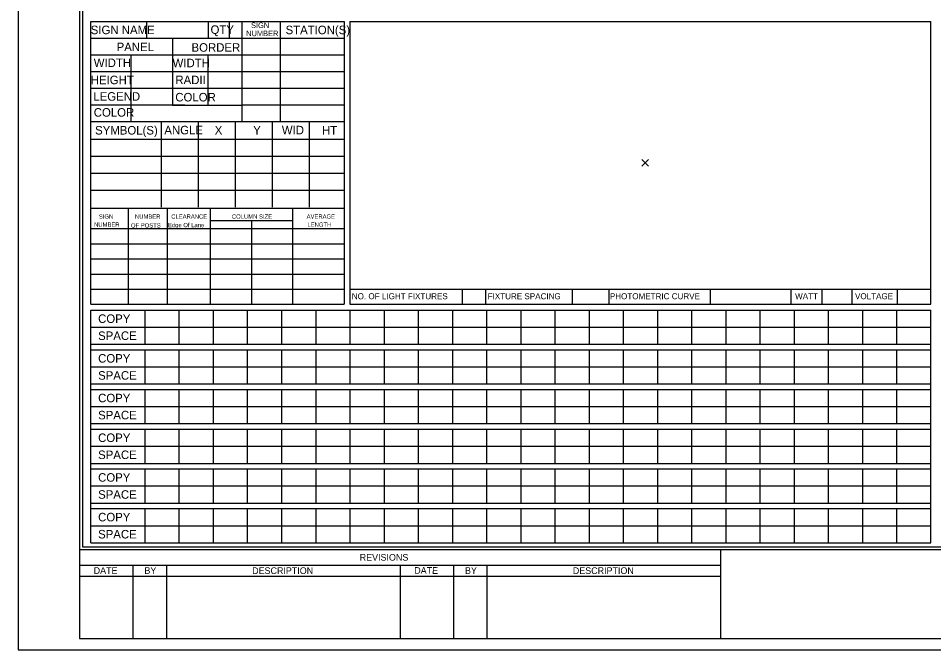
# Model space of a CAD drawing. Extents: x 1274.1 to 1363.1, y 833.5 to 890.6.
# Drawn here: x 1274.14 to 1318.48, y 833.48 to 864.07 of the extents above; entities that cross this region are included whole.
import ezdxf

# ---------------------------------------------------------------- set-up
doc = ezdxf.new("R2010")
doc.units = 0
for name, color, linetype in [('NonPlottingEle_dp', 7, 'Continuous'), ('PlotBorder_dp', 7, 'Continuous'), ('SheetBorder_dp', 7, 'Continuous'), ('SheetLines_dp', 7, 'Continuous'), ('SheetLinesMisc2_dp', 7, 'Continuous'), ('TextMinor', 7, 'Continuous'), ('TextMisc', 7, 'Continuous')]:
    doc.layers.add(name, color=color, linetype=linetype)

msp = doc.modelspace()

# ---------------------------------------------------------------- linework, layer by layer
at = {"layer": 'NonPlottingEle_dp'}
for p, q in [((1304.339, 857.226), (1304.66, 856.905)), ((1304.339, 856.905), (1304.66, 857.226))]:
    msp.add_line(p, q, dxfattribs=at)
at = {"layer": 'PlotBorder_dp'}
msp.add_lwpolyline([(1274.135, 833.481), (1363.097, 833.481), (1363.097, 890.634), (1274.135, 890.634)], close=True, dxfattribs=at)
at = {"layer": 'SheetBorder_dp'}
for p, q in [((1277.101, 890.095), (1277.101, 834.02)), ((1277.101, 838.334), (1360.132, 838.334)), ((1277.101, 834.02), (1360.132, 834.02))]:
    msp.add_line(p, q, dxfattribs=at)
at = {"layer": 'SheetLines_dp'}
for p, q in [((1308.156, 838.334), (1308.156, 834.02)), ((1277.101, 837.579), (1308.156, 837.579)), ((1279.689, 837.579), (1279.689, 834.02)), ((1281.306, 837.579), (1281.306, 834.02)), ((1292.628, 837.579), (1292.628, 834.02)), ((1295.216, 837.579), (1295.216, 834.02)), ((1296.834, 837.579), (1296.834, 834.02)), ((1277.101, 837.04), (1308.156, 837.04))]:
    msp.add_line(p, q, dxfattribs=at)
at = {"layer": 'SheetLinesMisc2_dp'}
for p, q in [((1277.247, 889.967), (1277.247, 838.462)), ((1277.644, 850.212), (1277.644, 863.919)), ((1277.644, 863.919), (1289.912, 863.919)), ((1280.348, 863.919), (1280.348, 863.109)), ((1283.331, 863.919), (1283.331, 863.109)), ((1284.349, 863.919), (1284.349, 863.109)), ((1284.956, 863.919), (1284.956, 859.061)), ((1286.823, 863.919), (1286.823, 859.061)), ((1289.912, 863.919), (1289.912, 850.212)), ((1290.195, 863.919), (1318.336, 863.919)), ((1290.195, 863.919), (1290.195, 850.231)), ((1318.336, 850.231), (1318.336, 863.92)), ((1277.644, 863.109), (1289.912, 863.109)), ((1281.609, 863.109), (1281.609, 859.862)), ((1277.644, 862.3), (1289.912, 862.3)), ((1279.583, 862.3), (1279.583, 859.061)), ((1283.32, 862.291), (1283.32, 859.862)), ((1277.644, 861.49), (1289.912, 861.49)), ((1277.644, 860.68), (1289.912, 860.68)), ((1277.644, 859.871), (1282.194, 859.871)), ((1281.609, 859.862), (1284.956, 859.862)), ((1284.956, 859.871), (1289.912, 859.871)), ((1277.644, 859.061), (1289.912, 859.061)), ((1281.051, 859.045), (1281.051, 854.911)), ((1282.844, 859.045), (1282.844, 854.911)), ((1284.636, 859.045), (1284.636, 854.911)), ((1286.429, 859.045), (1286.429, 854.911)), ((1288.221, 859.045), (1288.221, 854.911)), ((1277.647, 858.218), (1289.912, 858.218)), ((1277.647, 857.391), (1289.912, 857.391)), ((1277.647, 856.565), (1289.912, 856.565)), ((1277.647, 855.738), (1289.912, 855.738)), ((1277.644, 854.872), (1289.912, 854.872)), ((1279.464, 854.872), (1279.464, 850.212)), ((1281.346, 854.872), (1281.346, 850.212)), ((1283.424, 854.872), (1283.424, 850.212)), ((1287.425, 854.872), (1287.425, 850.212)), ((1283.424, 854.279), (1287.422, 854.279)), ((1285.432, 854.279), (1285.432, 850.212)), ((1277.644, 853.884), (1289.912, 853.884)), ((1277.644, 853.149), (1289.912, 853.149)), ((1277.644, 852.415), (1289.912, 852.415)), ((1277.644, 851.68), (1289.912, 851.68)), ((1277.644, 850.946), (1289.912, 850.946)), ((1290.196, 850.946), (1318.336, 850.946)), ((1295.631, 850.946), (1295.631, 850.212)), ((1296.77, 850.946), (1296.77, 850.212)), ((1300.96, 850.946), (1300.96, 850.212)), ((1302.744, 850.946), (1302.744, 850.212)), ((1307.643, 850.946), (1307.643, 850.212)), ((1311.554, 850.946), (1311.554, 850.212)), ((1313.064, 850.946), (1313.064, 850.212)), ((1314.519, 850.946), (1314.519, 850.212)), ((1316.711, 850.946), (1316.711, 850.212)), ((1277.644, 850.212), (1289.912, 850.212)), ((1290.195, 850.231), (1290.195, 850.213)), ((1290.196, 850.212), (1318.336, 850.212)), ((1318.336, 850.213), (1318.336, 850.231)), ((1277.644, 849.93), (1318.336, 849.93)), ((1277.644, 838.662), (1277.644, 849.93)), ((1280.263, 849.93), (1280.263, 848.276)), ((1281.919, 849.93), (1281.919, 848.276)), ((1283.574, 849.93), (1283.574, 848.276)), ((1285.229, 849.93), (1285.229, 848.276)), ((1286.885, 849.93), (1286.885, 848.276)), ((1288.54, 849.93), (1288.54, 848.276)), ((1290.196, 849.93), (1290.196, 848.276)), ((1291.851, 849.93), (1291.851, 848.276)), ((1293.506, 849.93), (1293.506, 848.276)), ((1295.161, 849.93), (1295.161, 848.276)), ((1296.817, 849.93), (1296.817, 848.276)), ((1298.472, 849.93), (1298.472, 848.276)), ((1300.127, 849.93), (1300.127, 848.276)), ((1301.783, 849.93), (1301.783, 848.276)), ((1303.438, 849.93), (1303.438, 848.276)), ((1305.093, 849.93), (1305.093, 848.276)), ((1306.749, 849.93), (1306.749, 848.276)), ((1308.404, 849.93), (1308.404, 848.276)), ((1310.06, 849.93), (1310.06, 848.276)), ((1311.715, 849.93), (1311.715, 848.276)), ((1313.37, 849.93), (1313.37, 848.276)), ((1315.025, 849.93), (1315.025, 848.276)), ((1316.681, 849.93), (1316.681, 848.276)), ((1318.336, 838.662), (1318.336, 849.93)), ((1277.644, 849.103), (1318.336, 849.103)), ((1277.644, 848.276), (1318.336, 848.276)), ((1277.644, 848.007), (1318.336, 848.007)), ((1280.263, 848.007), (1280.263, 846.353)), ((1281.919, 848.007), (1281.919, 846.353)), ((1283.574, 848.007), (1283.574, 846.353)), ((1285.229, 848.007), (1285.229, 846.353)), ((1286.885, 848.007), (1286.885, 846.353)), ((1288.54, 848.007), (1288.54, 846.353)), ((1290.196, 848.007), (1290.196, 846.353)), ((1291.851, 848.007), (1291.851, 846.353)), ((1293.506, 848.007), (1293.506, 846.353)), ((1295.161, 848.007), (1295.161, 846.353)), ((1296.817, 848.007), (1296.817, 846.353)), ((1298.472, 848.007), (1298.472, 846.353)), ((1300.127, 848.007), (1300.127, 846.353)), ((1301.783, 848.007), (1301.783, 846.353)), ((1303.438, 848.007), (1303.438, 846.353)), ((1305.093, 848.007), (1305.093, 846.353)), ((1306.749, 848.007), (1306.749, 846.353)), ((1308.404, 848.007), (1308.404, 846.353)), ((1310.06, 848.007), (1310.06, 846.353)), ((1311.715, 848.007), (1311.715, 846.353)), ((1313.37, 848.007), (1313.37, 846.353)), ((1315.025, 848.007), (1315.025, 846.353)), ((1316.681, 848.007), (1316.681, 846.353)), ((1277.644, 847.18), (1318.336, 847.18)), ((1277.644, 846.353), (1318.336, 846.353)), ((1277.644, 846.084), (1318.336, 846.084)), ((1280.263, 846.084), (1280.263, 844.431)), ((1281.919, 846.084), (1281.919, 844.431)), ((1283.574, 846.084), (1283.574, 844.431)), ((1285.229, 846.084), (1285.229, 844.431)), ((1286.885, 846.084), (1286.885, 844.431)), ((1288.54, 846.084), (1288.54, 844.431)), ((1290.196, 846.084), (1290.196, 844.431)), ((1291.851, 846.084), (1291.851, 844.431)), ((1293.506, 846.084), (1293.506, 844.431)), ((1295.161, 846.084), (1295.161, 844.431)), ((1296.817, 846.084), (1296.817, 844.431)), ((1298.472, 846.084), (1298.472, 844.431)), ((1300.127, 846.084), (1300.127, 844.431)), ((1301.783, 846.084), (1301.783, 844.431)), ((1303.438, 846.084), (1303.438, 844.431)), ((1305.093, 846.084), (1305.093, 844.431)), ((1306.749, 846.084), (1306.749, 844.431)), ((1308.404, 846.084), (1308.404, 844.431)), ((1310.06, 846.084), (1310.06, 844.431)), ((1311.715, 846.084), (1311.715, 844.431)), ((1313.37, 846.084), (1313.37, 844.431)), ((1315.025, 846.084), (1315.025, 844.431)), ((1316.681, 846.084), (1316.681, 844.431)), ((1277.644, 845.257), (1318.336, 845.257)), ((1277.644, 844.431), (1318.336, 844.431)), ((1277.644, 844.161), (1318.336, 844.161)), ((1280.263, 844.161), (1280.263, 842.508)), ((1281.919, 844.161), (1281.919, 842.508)), ((1283.574, 844.161), (1283.574, 842.508)), ((1285.229, 844.161), (1285.229, 842.508)), ((1286.885, 844.161), (1286.885, 842.508)), ((1288.54, 844.161), (1288.54, 842.508)), ((1290.196, 844.161), (1290.196, 842.508)), ((1291.851, 844.161), (1291.851, 842.508)), ((1293.506, 844.161), (1293.506, 842.508)), ((1295.161, 844.161), (1295.161, 842.508)), ((1296.817, 844.161), (1296.817, 842.508)), ((1298.472, 844.161), (1298.472, 842.508)), ((1300.127, 844.161), (1300.127, 842.508)), ((1301.783, 844.161), (1301.783, 842.508)), ((1303.438, 844.161), (1303.438, 842.508)), ((1305.093, 844.161), (1305.093, 842.508)), ((1306.749, 844.161), (1306.749, 842.508)), ((1308.404, 844.161), (1308.404, 842.508)), ((1310.06, 844.161), (1310.06, 842.508)), ((1311.715, 844.161), (1311.715, 842.508)), ((1313.37, 844.161), (1313.37, 842.508)), ((1315.025, 844.161), (1315.025, 842.508)), ((1316.681, 844.161), (1316.681, 842.508)), ((1277.644, 843.335), (1318.336, 843.335)), ((1277.644, 842.508), (1318.336, 842.508)), ((1277.644, 842.238), (1318.336, 842.238)), ((1280.263, 842.238), (1280.263, 840.585)), ((1281.919, 842.238), (1281.919, 840.585)), ((1283.574, 842.238), (1283.574, 840.585)), ((1285.229, 842.238), (1285.229, 840.585)), ((1286.885, 842.238), (1286.885, 840.585)), ((1288.54, 842.238), (1288.54, 840.585)), ((1290.196, 842.238), (1290.196, 840.585)), ((1291.851, 842.238), (1291.851, 840.585)), ((1293.506, 842.238), (1293.506, 840.585)), ((1295.161, 842.238), (1295.161, 840.585)), ((1296.817, 842.238), (1296.817, 840.585)), ((1298.472, 842.238), (1298.472, 840.585)), ((1300.127, 842.238), (1300.127, 840.585)), ((1301.783, 842.238), (1301.783, 840.585)), ((1303.438, 842.238), (1303.438, 840.585)), ((1305.093, 842.238), (1305.093, 840.585)), ((1306.749, 842.238), (1306.749, 840.585)), ((1308.404, 842.238), (1308.404, 840.585)), ((1310.06, 842.238), (1310.06, 840.585)), ((1311.715, 842.238), (1311.715, 840.585)), ((1313.37, 842.238), (1313.37, 840.585)), ((1315.025, 842.238), (1315.025, 840.585)), ((1316.681, 842.238), (1316.681, 840.585)), ((1277.644, 841.411), (1318.336, 841.411)), ((1277.644, 840.585), (1318.336, 840.585)), ((1277.644, 840.315), (1318.336, 840.315)), ((1280.263, 840.315), (1280.263, 838.662)), ((1281.919, 840.315), (1281.919, 838.662)), ((1283.574, 840.315), (1283.574, 838.662)), ((1285.229, 840.315), (1285.229, 838.662)), ((1286.885, 840.315), (1286.885, 838.662)), ((1288.54, 840.315), (1288.54, 838.662)), ((1290.196, 840.315), (1290.196, 838.662)), ((1291.851, 840.315), (1291.851, 838.662)), ((1293.506, 840.315), (1293.506, 838.662)), ((1295.161, 840.315), (1295.161, 838.662)), ((1296.817, 840.315), (1296.817, 838.662)), ((1298.472, 840.315), (1298.472, 838.662)), ((1300.127, 840.315), (1300.127, 838.662)), ((1301.783, 840.315), (1301.783, 838.662)), ((1303.438, 840.315), (1303.438, 838.662)), ((1305.093, 840.315), (1305.093, 838.662)), ((1306.749, 840.315), (1306.749, 838.662)), ((1308.404, 840.315), (1308.404, 838.662)), ((1310.06, 840.315), (1310.06, 838.662)), ((1311.715, 840.315), (1311.715, 838.662)), ((1313.37, 840.315), (1313.37, 838.662)), ((1315.025, 840.315), (1315.025, 838.662)), ((1316.681, 840.315), (1316.681, 838.662)), ((1277.644, 839.489), (1318.336, 839.489)), ((1277.644, 838.662), (1318.336, 838.662)), ((1277.247, 838.462), (1359.988, 838.462))]:
    msp.add_line(p, q, dxfattribs=at)

# ---------------------------------------------------------------- texts
at = {"layer": 'TextMinor'}
for s, height, p in [('SIGN', 0.2696, (1285.407, 863.594)), ('SIGN NAME', 0.4125, (1277.644, 863.299)), ('QTY', 0.4125, (1283.448, 863.313)), ('NUMBER', 0.2696, (1285.172, 863.202)), ('STATION(S)', 0.4125, (1287.081, 863.297)), ('PANEL', 0.4125, (1278.898, 862.476)), ('BORDER', 0.4125, (1282.526, 862.448)), ('WIDTH', 0.4125, (1277.79, 861.706)), ('WIDTH', 0.4125, (1281.609, 861.697)), ('HEIGHT', 0.4125, (1277.644, 860.876)), ('RADII', 0.4125, (1281.744, 860.877)), ('LEGEND', 0.4125, (1277.768, 860.075)), ('COLOR', 0.4125, (1281.741, 860.04)), ('COLOR', 0.4125, (1277.79, 859.302)), ('SYMBOL(S)', 0.4125, (1277.855, 858.437)), ('ANGLE', 0.4125, (1281.209, 858.446)), ('X', 0.412, (1283.65, 858.437)), ('Y', 0.412, (1285.514, 858.437)), ('WID', 0.4125, (1286.902, 858.446)), ('HT', 0.4125, (1288.845, 858.438)), ('SIGN', 0.2062, (1278.037, 854.363)), ('NUMBER', 0.2062, (1279.788, 854.36)), ('CLEARANCE', 0.2062, (1281.544, 854.362)), ('COLUMN SIZE', 0.20623, (1284.483, 854.362)), ('AVERAGE', 0.2062, (1288.101, 854.362)), ('NUMBER', 0.2062, (1277.806, 853.971)), ('OF POSTS', 0.2062, (1279.593, 853.932)), ('Edge Of Lane', 0.20623, (1281.385, 853.947)), ('LENGTH', 0.2062, (1288.14, 853.971)), ('NO. OF LIGHT FIXTURES', 0.2923, (1290.29, 850.458)), ('FIXTURE SPACING', 0.2923, (1296.871, 850.458)), ('PHOTOMETRIC CURVE', 0.2923, (1302.79, 850.458)), ('WATT', 0.2923, (1311.763, 850.458)), ('VOLTAGE', 0.2923, (1314.665, 850.458)), ('COPY', 0.4125, (1278.001, 849.311)), ('SPACE', 0.4125, (1278.001, 848.485)), ('COPY', 0.4125, (1278.001, 847.388)), ('SPACE', 0.4125, (1278.001, 846.561)), ('COPY', 0.4125, (1278.001, 845.466)), ('SPACE', 0.4125, (1278.001, 844.639)), ('COPY', 0.4125, (1278.001, 843.542)), ('SPACE', 0.4125, (1278.001, 842.716)), ('COPY', 0.4125, (1278.001, 841.619)), ('SPACE', 0.4125, (1278.001, 840.793)), ('COPY', 0.4125, (1278.001, 839.697)), ('SPACE', 0.4125, (1278.001, 838.87))]:
    msp.add_text(s, height=height, dxfattribs=at).set_placement(p)
at = {"layer": 'TextMisc'}
for s, p in [('REVISIONS', (1290.672, 837.794)), ('BY', (1280.244, 837.153)), ('BY', (1295.772, 837.153))]:
    msp.add_text(s, height=0.3235, dxfattribs=at).set_placement(p)
for s, height, rotation, p in [('DATE', 0.3235, 359.8692, (1277.786, 837.153)), ('DESCRIPTION', 0.32343, 0.0498, (1285.463, 837.147)), ('DATE', 0.3235, 359.8692, (1293.314, 837.158)), ('DESCRIPTION', 0.32343, 0.0498, (1300.997, 837.147))]:
    msp.add_text(s, height=height, rotation=rotation, dxfattribs=at).set_placement(p)

doc.saveas('drawing.dxf')
